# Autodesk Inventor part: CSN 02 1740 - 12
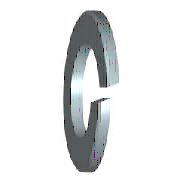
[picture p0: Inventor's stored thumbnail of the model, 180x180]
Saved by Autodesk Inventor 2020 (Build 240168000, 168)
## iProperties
Created: 2019-01
Part Number: CSN 02 1740 - 12
Material: Ocel, měkká
Description: Pružné podložky čtvercového průřezu
Document SubType Name: Modeling
Standard: CSN 02 1740
Designer: doma
Standards Organization: CSN
Language: cs-CZ
Size Designation: 12
Categories: <MemberInstance><Categories><Category DisplayName="Spojovací materiál" InternalName="e4da775c-781d-43d5-af7c-5136215cf5a6" Mnemonic="FSTN"><Category DisplayName
Density: 7.85 g/cm^3
Appearance: Pololeštěná
Mass: 2.21664 g
Surface Area: 4.64529 cm^2
Volume: 0.282375 cm^3
IsCustomPart: 0
Author: doma
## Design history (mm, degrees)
sketch "Náčrt1"
  geometry: C1 r 8.6 at (0, 0); C2 r 6.1 at (0, 0); 1 further point
  constraints: 2 centre point, 2 coincident
  dimensions: "d0" = 12.2 diameter of C2 (= SD1); "d1" = 17.2 diameter of C1 (= SD2)
extrude "Těleso" new body sketch "Náčrt1" distance "d2" = 2.5 (= SD); taper "d3" = 0 deg
sketch "Náčrt2"
  geometry: L1 (0, -6.1)-(0, 6.1) reference; L2 (2.5, 8.6)-(2.5, -8.6) reference; L3 (-1.2, 0)-(7.2, 0) reference; L4 (0, -0.5)-(2.5, -0.059); L5 (0, 0.5)-(2.5, 0.941)
  constraints: 4 end point, 4 point on line, 1 parallel
  dimensions: "d4" = 0.5 distance from line of L3 L4.start (= 0.2 x SD); "d5" = 0.5 distance from line of L3 L5.start (= 0.2 x SD); "d6" = 80 deg angle of L2 L4 (= FAWI)
extrude "Výřez" cut sketch "Náčrt2" stored distance "d7" = 2.5 (= SD); taper "d8" = 0 deg
workaxis "Work Axis1"
workplane "Work Plane1"
body "Solid1"
other parameters: "SD1" = 12.2 [user parameter; used in 1 equation term], "SD2" = 17.2 [user parameter; used in 1 equation term], "SD" = 2.5 [user parameter; used in 4 equation terms], "FAWI" = 80 deg [user parameter; used in 1 equation term], "d9" = 0, "d10" = 0, "d11" = 0, "d12" = 0, "NND" = 12 [user parameter]
